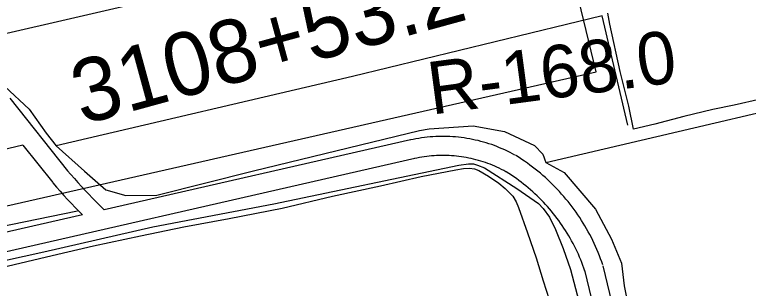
# Model space of a CAD drawing. Extents: x 3392644 to 3430565, y 576657 to 602123.
# Drawn here: x 3415223 to 3416383, y 584134 to 584566 of the extents above; entities that cross this region are included whole.
import ezdxf

# ---------------------------------------------------------------- set-up
doc = ezdxf.new("R2010")
doc.units = 0
for name, color, linetype in [('V-RIVR-RANG-IDEN', 7, 'Continuous'), ('V-ROAD-CNTR', 7, 'Continuous'), ('V-SITE-OTLN', 7, 'Continuous'), ('V-SITE-VEGE', 7, 'Continuous'), ('V-SURV-IDEN', 7, 'Continuous'), ('V-TOPO-SHOR', 7, 'Continuous'), ('V-UTIL-LINE', 7, 'Continuous')]:
    doc.layers.add(name, color=color, linetype=linetype)

msp = doc.modelspace()

# ---------------------------------------------------------------- linework, layer by layer
at = {"layer": 'V-ROAD-CNTR'}
for points in [[(3415215, 584433.9), (3415306.4, 584319.2)], [(3416014.2, 584344.1), (3416010.4, 584346.2), (3416006.4, 584348.2), (3416002.3, 584350.2), (3415998.3, 584352.1), (3415994.1, 584353.9), (3415990, 584355.7), (3415985.8, 584357.4), (3415981.6, 584359), (3415977.4, 584360.5), (3415973.1, 584361.9), (3415968.8, 584363.2), (3415964.5, 584364.5), (3415960.2, 584365.7), (3415955.8, 584366.8), (3415951.4, 584367.8), (3415947, 584368.7), (3415942.6, 584369.6), (3415938.2, 584370.4), (3415933.7, 584371.1), (3415929.3, 584371.6), (3415924.8, 584372.2), (3415920.3, 584372.6), (3415915.8, 584372.9), (3415911.4, 584373.2), (3415906.9, 584373.4), (3415902.4, 584373.5), (3415897.9, 584373.5), (3415893.4, 584373.4), (3415888.9, 584373.2), (3415884.4, 584373), (3415879.9, 584372.6), (3415875.4, 584372.2), (3415870.9, 584371.7), (3415866.5, 584371.1), (3415862, 584370.4), (3415857.6, 584369.6), (3415853.2, 584368.8), (3415849.4, 584368)], [(3415235.7, 584359.8), (3415002.8, 584304.2)], [(3415235.7, 584359.8), (3415282.9, 584300.5)], [(3415849.1, 584367.9), (3415364.5, 584257.5)], [(3415855.8, 584338.7), (3415038.3, 584152.4)], [(3416000, 584317.7), (3415996.4, 584319.6), (3415992.9, 584321.4), (3415989.4, 584323.2), (3415985.8, 584324.8), (3415982.2, 584326.4), (3415978.6, 584327.9), (3415975, 584329.4), (3415971.3, 584330.8), (3415967.6, 584332.1), (3415963.9, 584333.4), (3415960.1, 584334.5), (3415956.3, 584335.6), (3415952.5, 584336.7), (3415948.7, 584337.6), (3415944.9, 584338.5), (3415941.1, 584339.3), (3415937.2, 584340.1), (3415933.3, 584340.8), (3415929.5, 584341.4), (3415925.6, 584341.9), (3415921.7, 584342.3), (3415917.8, 584342.7), (3415913.8, 584343), (3415909.9, 584343.2), (3415906, 584343.4), (3415902.1, 584343.5), (3415898.1, 584343.5), (3415894.2, 584343.4), (3415890.3, 584343.2), (3415886.4, 584343), (3415882.4, 584342.7), (3415878.5, 584342.3), (3415874.6, 584341.9), (3415870.7, 584341.4), (3415866.8, 584340.8), (3415863, 584340.1), (3415859.1, 584339.4), (3415855.5, 584338.6)], [(3416153.2, 584170.5), (3416151.6, 584175.3), (3416149.8, 584180.2), (3416147.9, 584185.1), (3416146, 584190), (3416143.9, 584194.8), (3416141.8, 584199.6), (3416139.7, 584204.3), (3416137.4, 584209), (3416135.1, 584213.7), (3416132.7, 584218.3), (3416130.2, 584222.9), (3416127.6, 584227.5), (3416125, 584232), (3416122.3, 584236.5), (3416119.5, 584240.9), (3416116.7, 584245.3), (3416113.8, 584249.6), (3416110.8, 584253.9), (3416107.8, 584258.2), (3416104.6, 584262.4), (3416101.5, 584266.5), (3416098.2, 584270.6), (3416094.9, 584274.6), (3416091.5, 584278.6), (3416088.1, 584282.5), (3416084.6, 584286.4), (3416081, 584290.2), (3416077.4, 584294), (3416073.7, 584297.7), (3416070, 584301.3), (3416066.2, 584304.9), (3416062.3, 584308.4), (3416058.4, 584311.9), (3416054.4, 584315.3), (3416050.4, 584318.6), (3416046.3, 584321.9), (3416042.2, 584325.1), (3416038, 584328.2), (3416033.8, 584331.3), (3416029.5, 584334.2), (3416025.1, 584337.2), (3416020.8, 584340), (3416016.4, 584342.8), (3416015, 584343.7)], [(3415306, 584319.6), (3415311.6, 584313.2), (3415317.2, 584306.9), (3415322.8, 584300.6), (3415328.5, 584294.4), (3415334.3, 584288.3), (3415340.1, 584282.2), (3415346, 584276.1), (3415364.5, 584257.5)], [(3416124.9, 584160.7), (3416123.3, 584165.3), (3416121.7, 584169.7), (3416120, 584174.2), (3416118.2, 584178.6), (3416116.4, 584182.9), (3416114.5, 584187.3), (3416112.5, 584191.6), (3416110.4, 584195.9), (3416108.3, 584200.1), (3416106.1, 584204.3), (3416103.9, 584208.5), (3416101.6, 584212.6), (3416099.2, 584216.7), (3416096.7, 584220.8), (3416094.2, 584224.8), (3416091.7, 584228.8), (3416089, 584232.7), (3416086.3, 584236.6), (3416083.5, 584240.5), (3416080.7, 584244.3), (3416077.8, 584248), (3416074.9, 584251.7), (3416071.9, 584255.4), (3416068.8, 584259), (3416065.7, 584262.6), (3416062.5, 584266.1), (3416059.3, 584269.6), (3416056, 584273), (3416052.6, 584276.3), (3416049.2, 584279.6), (3416045.8, 584282.9), (3416042.3, 584286.1), (3416038.7, 584289.2), (3416035.1, 584292.3), (3416031.4, 584295.3), (3416027.7, 584298.3), (3416024, 584301.2), (3416020.2, 584304), (3416016.4, 584306.8), (3416012.5, 584309.5), (3416008.5, 584312.2), (3416004.6, 584314.8), (3416000.5, 584317.3), (3415999.2, 584318.1)], [(3415283.3, 584300), (3415289, 584293.4), (3415294.8, 584286.9), (3415300.6, 584280.4), (3415306.5, 584274), (3415312.5, 584267.7), (3415318.5, 584261.4), (3415329.9, 584249.6)], [(3415329.9, 584249.6), (3415031.7, 584181.6)], [(3416209.1, 583813.2), (3416124.5, 584162.1)], [(3416199.2, 583981.1), (3416153.7, 584169.1)]]:
    msp.add_lwpolyline(points, dxfattribs=at)
at = {"layer": 'V-SITE-OTLN'}
msp.add_lwpolyline([(3416402.9, 584432.3), (3416361.2, 584422.9), (3416327.4, 584415.9), (3416281.5, 584405.1), (3416235.3, 584393.1), (3416201.9, 584385), (3416194.5, 584421.5), (3416180.9, 584476.3), (3416164.3, 584550.7), (3416161.1, 584568)], dxfattribs=at)
at = {"layer": 'V-SITE-VEGE'}
msp.add_lwpolyline([(3415202, 584166.5), (3415281.9, 584185.4), (3415347.2, 584200.4), (3415421.6, 584216.3), (3415490.5, 584230.5), (3415562.1, 584243.9), (3415645.9, 584260.3), (3415725.3, 584278.9), (3415801.4, 584295.6), (3415866, 584310.2), (3415920.8, 584320.5), (3415932.7, 584323), (3415942.2, 584323.5), (3415950.3, 584322.1), (3415957.2, 584319.5), (3415972.2, 584310.9), (3415988.6, 584299.6), (3415998.5, 584291.4), (3416005.3, 584284.9), (3416010.9, 584278.9), (3416016.1, 584270.4), (3416020, 584261), (3416033.9, 584221.3), (3416047.9, 584181.8), (3416058.7, 584145.2), (3416068.4, 584116)], dxfattribs=at)
at = {"layer": 'V-TOPO-SHOR'}
msp.add_line((3415322.3, 584255.4), (3415120.4, 584214.3), dxfattribs=at)
for points in [[(3415085.2, 584609.3), (3415094.3, 584582.4), (3416106.1, 584812.9), (3416122.1, 584745.6), (3416077.2, 584736.4), (3415168.6, 584526.6), (3415139.4, 584535.4), (3414977.9, 584496.7), (3414971, 584532.6), (3414973.2, 584552.8), (3414975.4, 584573), (3414977.6, 584575.3)], [(3416063, 584332.2), (3416657.5, 584471.4), (3416908.8, 584528.4), (3417438.2, 584649.3), (3417706.1, 584716.2), (3417738.9, 584722.3)], [(3416193, 584391.1), (3416152, 584563.8), (3415757.1, 584468.1), (3415288.2, 584358.6), (3415333.3, 584318.4), (3415367.1, 584289.3), (3415398.5, 584280.4), (3415447.9, 584280.6), (3415600.5, 584319.3), (3415863, 584383.1), (3415878.7, 584385.5)], [(3415112.7, 584481.5), (3415171.1, 584468.2), (3415207.1, 584452.6), (3415245.4, 584416.8), (3415272.4, 584378.8), (3415288.2, 584358.6)], [(3415878.7, 584385.5), (3415948.3, 584390.2), (3415997.7, 584381.4), (3416044.9, 584359.1), (3416058.4, 584345.7), (3416063, 584332.2), (3416092.2, 584316.6), (3416141.8, 584258.4), (3416166.7, 584211.4), (3416182.6, 584173.2), (3416187.2, 584137.3), (3416219.2, 583978), (3416243.9, 583969.1), (3416270.9, 583976), (3416291.1, 583978.3)], [(3415175.1, 584170.8), (3415269, 584191.4), (3415441.1, 584230.8), (3415632.9, 584267.1), (3415925.6, 584328), (3415940.6, 584330.4), (3415948.8, 584330.2), (3415954.9, 584328), (3415965.8, 584323.7), (3416017, 584291.3), (3416051.3, 584267.4), (3416058.6, 584259.7), (3416068.6, 584245.8), (3416078.4, 584226.5), (3416090.7, 584196.3), (3416102.3, 584163.3), (3416130.8, 584055.5)]]:
    msp.add_lwpolyline(points, dxfattribs=at)
at = {"layer": 'V-UTIL-LINE'}
msp.add_lwpolyline([(3412089.9, 582100), (3412531, 582457.8), (3414603.6, 584199.2), (3415068.6, 584289.5), (3415163.5, 584253.5), (3416142.9, 584475.3), (3415963.7, 585214)], dxfattribs=at)

# ---------------------------------------------------------------- texts
at = {"layer": 'V-RIVR-RANG-IDEN'}
msp.add_text('R-168.0', height=83, rotation=7.5908, dxfattribs=at).set_placement((3415882.2, 584407.7))
at = {"layer": 'V-SURV-IDEN'}
msp.add_text('3108+53.2', height=100, rotation=15.2822, dxfattribs=at).set_placement((3415329.3, 584391.4))

doc.saveas('drawing.dxf')
